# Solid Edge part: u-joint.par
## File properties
Title: Ypke
Author: Deepak Maini
Template: normal.par
Last saved by: Robert a Rhodes jr
Revision: 7
Application: Solid Edge
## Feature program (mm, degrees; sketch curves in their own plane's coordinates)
sketch for "unnamed Protrusion 1" plane through (0, 0, 0) normal (0, -1, 0) x-axis (1, 0, 0)
  line (-44.45, -33.7976) -> (-44.45, 4.3024)
  arc centre (0, 4.3024) radius 44.45 from (-44.45, 4.3024) to (44.45, 4.3024) cw
  line (44.45, 4.3024) -> (44.45, -33.7976)
  line (44.45, -33.7976) -> (25.4, -33.7976)
  line (25.4, -33.7976) -> (25.4, 4.3024)
  arc centre (0, 4.3024) radius 25.4 from (-25.4, 4.3024) to (25.4, 4.3024) cw
  line (-25.4, -33.7976) -> (-25.4, 4.3024)
  line (-44.45, -33.7976) -> (-25.4, -33.7976)
extrude "unnamed Protrusion 1" add finite 50.8 along -normal
fillet "unnamed Round 1"
sketch for "unnamed Hole 1" plane through (44.45, 25.4, -14.7476) normal (1, 0, 0) x-axis (0, 1, 0)
  hole centre (0, 6.35) bore radius 9.525
hole "unnamed Hole 1" through
sketch for "unnamed Protrusion 2" plane through (46.6729, 25.4, 119.8724) normal (0, 0, 1) x-axis (-1, 0, 0)
  circle centre (46.6729, 0) radius 17.1196
extrude "unnamed Protrusion 2" add
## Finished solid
Body 1: solid body, 14 faces, 30 edges, 16 vertices.
  Faces by surface: cylinder 7, plane 7
  Edges by curve: line 16, circle 13, intersection 1
Bounding box of the edges (mm): 88.900 x 50.800 x 153.670, from (-44.45, 0, -33.7976) to (44.45, 50.8, 119.8724).
Cylindrical faces by radius (mm): R9.525 x2, R17.1196 x1, R25.4 x3, R44.45 x1
Planar faces by outward normal: +x 2, +y 1, +z 1, -x 2, -y 1
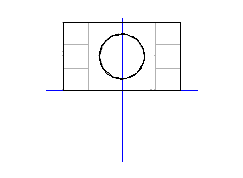
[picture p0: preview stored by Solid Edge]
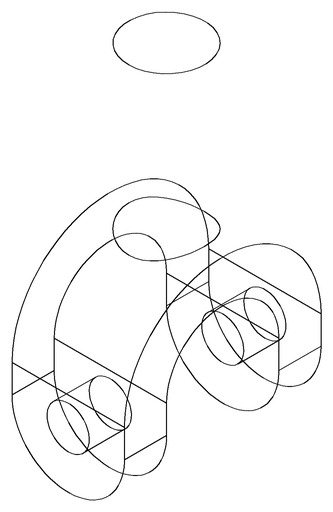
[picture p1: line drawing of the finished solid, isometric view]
